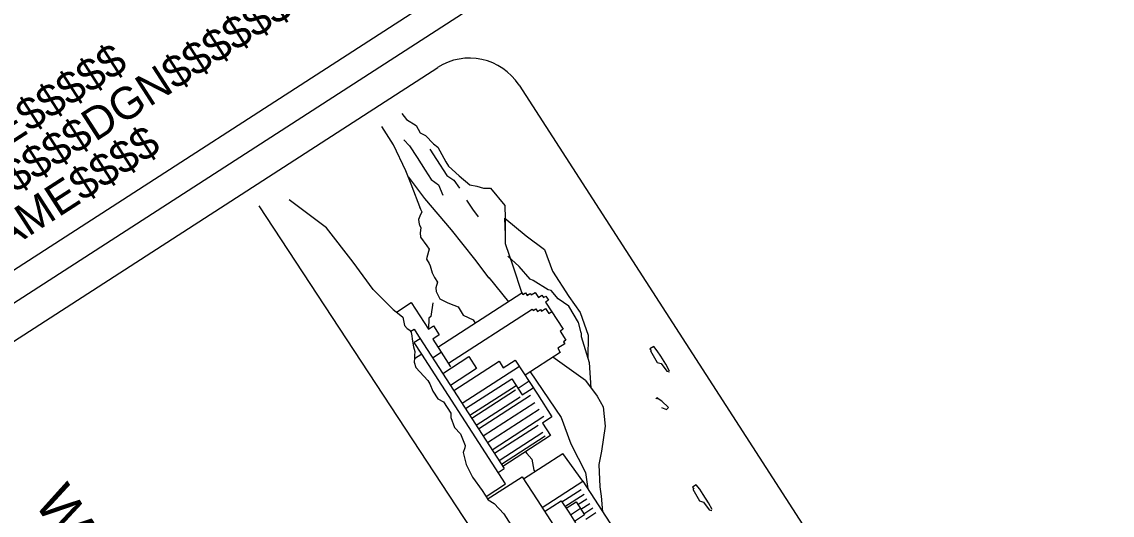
# Model space of a CAD drawing. Extents: x 2160312 to 2162215, y 789569 to 792090.
# Drawn here: x 2160524.6 to 2160714.6, y 791352.1 to 791438.1 of the extents above; entities that cross this region are included whole.
import ezdxf

# ---------------------------------------------------------------- set-up
doc = ezdxf.new("R2010")
doc.units = 0
doc.layers.add('DEV TITLE SHEET CELL', color=7, linetype='Continuous')

msp = doc.modelspace()

# ---------------------------------------------------------------- linework, layer by layer
at = {"layer": 'DEV TITLE SHEET CELL'}
for p, q in [((2161358.45, 791933.98), (2160493.62, 791375.7)), ((2161356.83, 791927.18), (2160500.69, 791374.51)), ((2160507.83, 791372.54), (2160597.07, 791430.14)), ((2160611.25, 791427.06), (2161126.03, 790629.59)), ((2160590.84, 791422.12), (2160591.61, 791421.06)), ((2160589.39, 791416.64), (2160587.32, 791419.85)), ((2160591.61, 791421.06), (2160593.32, 791420.05)), ((2160593.32, 791420.05), (2160594.01, 791418.77)), ((2160591.17, 791417.53), (2160592.16, 791416.49)), ((2160594.01, 791418.77), (2160594.96, 791418.32)), ((2160594.96, 791418.32), (2160596.33, 791416.82)), ((2160591.51, 791412.14), (2160589.39, 791416.64)), ((2160592.16, 791416.49), (2160593.49, 791414.43)), ((2160595.73, 791415.89), (2160596.88, 791414.11)), ((2160596.33, 791416.82), (2160597.09, 791416.26)), ((2160597.09, 791416.26), (2160598.47, 791413.71)), ((2160593.49, 791414.43), (2160594.88, 791412.28)), ((2160596.88, 791414.11), (2160598.69, 791411.3)), ((2160592.44, 791409.8), (2160591.51, 791412.14)), ((2160594.88, 791412.28), (2160595.96, 791410.6)), ((2160598.47, 791413.71), (2160598.95, 791412.96)), ((2160598.95, 791412.96), (2160600.84, 791411.27)), ((2160591.98, 791411.03), (2160594.77, 791407.32)), ((2160595.96, 791410.6), (2160597.22, 791409.69)), ((2160598.69, 791411.3), (2160599.88, 791410.48)), ((2160599.88, 791410.48), (2160600.88, 791409.14)), ((2160600.84, 791411.27), (2160602.67, 791409.67)), ((2160594.12, 791405.4), (2160592.44, 791409.8)), ((2160597.22, 791409.69), (2160597.96, 791407.92)), ((2160602.67, 791409.67), (2160603.88, 791409.45)), ((2160603.88, 791409.45), (2160605.05, 791409.09)), ((2160605.05, 791409.09), (2160606.26, 791409.11)), ((2160606.26, 791409.11), (2160608.75, 791406.12)), ((2160594.77, 791407.32), (2160599.42, 791401.87)), ((2160602.11, 791407.03), (2160603.14, 791405.44)), ((2160608.75, 791406.12), (2160608.83, 791403.82)), ((2160624.28, 791317.21), (2160565.96, 791406.06)), ((2160593.98, 791404.24), (2160593.7, 791403.66)), ((2160593.93, 791405.83), (2160594.3, 791404.97)), ((2160594.3, 791404.97), (2160593.98, 791404.24)), ((2160603.14, 791405.44), (2160604.14, 791404.1)), ((2160593.7, 791403.66), (2160593.84, 791402.82)), ((2160593.84, 791402.82), (2160593.9, 791402.73)), ((2160593.9, 791402.73), (2160594.11, 791402.2)), ((2160608.83, 791403.82), (2160608.84, 791399.49)), ((2160594.11, 791402.2), (2160594, 791401.34)), ((2160594, 791401.34), (2160594.08, 791400.6)), ((2160594.08, 791400.6), (2160595.2, 791399.07)), ((2160599.42, 791401.87), (2160603.5, 791396.72)), ((2160595.2, 791399.07), (2160595.56, 791398.51)), ((2160608.84, 791399.49), (2160610.17, 791395.58)), ((2160595.17, 791397.06), (2160595.11, 791396.76)), ((2160595.11, 791396.76), (2160595.59, 791396.01)), ((2160595.56, 791398.51), (2160595.17, 791397.06)), ((2160603.5, 791396.72), (2160605.96, 791393.42)), ((2160611.25, 791395.44), (2160609.3, 791397.29)), ((2160615.66, 791398.42), (2160617.07, 791394.63)), ((2160595.59, 791396.01), (2160595.74, 791395.57)), ((2160595.74, 791395.57), (2160596.12, 791394.37)), ((2160610.17, 791395.58), (2160611.73, 791390.83)), ((2160613.17, 791393.25), (2160611.25, 791395.44)), ((2160596.12, 791394.37), (2160596.51, 791393.56)), ((2160596.51, 791393.56), (2160597.05, 791392.72)), ((2160605.99, 791393.55), (2160609.4, 791389.33)), ((2160613.7, 791393.02), (2160613.17, 791393.25)), ((2160616.32, 791391.42), (2160613.7, 791393.02)), ((2160617.07, 791394.63), (2160619.91, 791390.25)), ((2160597.05, 791392.72), (2160596.76, 791391.73)), ((2160596.76, 791391.73), (2160596.78, 791391.09)), ((2160596.78, 791391.09), (2160597.47, 791389.81)), ((2160613.34, 791390.51), (2160614.04, 791390.96)), ((2160614.04, 791390.96), (2160614.61, 791390.08)), ((2160616.87, 791391.26), (2160616.32, 791391.42)), ((2160618.06, 791389.81), (2160616.87, 791391.26)), ((2160589.87, 791387.52), (2160592.45, 791389.19)), ((2160592.45, 791389.19), (2160595.45, 791384.55)), ((2160596.2, 791389.12), (2160595.85, 791386.78)), ((2160597.11, 791381.4), (2160611.76, 791390.85)), ((2160597.47, 791389.81), (2160598.85, 791389.11)), ((2160598.85, 791389.11), (2160599.89, 791388.73)), ((2160611.76, 791390.85), (2160611.92, 791390.59)), ((2160611.92, 791390.59), (2160612.36, 791390.87)), ((2160612.36, 791390.87), (2160612.65, 791390.43)), ((2160612.65, 791390.43), (2160613.17, 791390.77)), ((2160612.79, 791390.7), (2160612.84, 791390.55)), ((2160613.17, 791390.77), (2160613.34, 791390.51)), ((2160614.61, 791390.08), (2160615.22, 791390.48)), ((2160615.22, 791390.48), (2160615.51, 791390.04)), ((2160615.51, 791390.04), (2160615.94, 791390.32)), ((2160616.4, 791389.62), (2160615.87, 791389.28)), ((2160615.87, 791389.28), (2160618.93, 791384.55)), ((2160615.94, 791390.32), (2160616.4, 791389.62)), ((2160619.9, 791388.53), (2160618.06, 791389.81)), ((2160619.91, 791390.25), (2160621.9, 791387.45)), ((2160589.32, 791387.96), (2160590.33, 791387.15)), ((2160590.33, 791387.15), (2160591, 791386.61)), ((2160598.96, 791378.62), (2160613.56, 791388.05)), ((2160599.89, 791388.73), (2160600.63, 791388.41)), ((2160600.63, 791388.41), (2160601.53, 791387.01)), ((2160613.56, 791388.05), (2160613.73, 791387.78)), ((2160613.73, 791387.78), (2160614.17, 791388.07)), ((2160614.17, 791388.07), (2160614.46, 791387.63)), ((2160614.46, 791387.63), (2160614.98, 791387.97)), ((2160614.98, 791387.97), (2160615.15, 791387.7)), ((2160615.15, 791387.7), (2160615.85, 791388.16)), ((2160615.85, 791388.16), (2160616.42, 791387.28)), ((2160616.42, 791387.28), (2160616.94, 791387.62)), ((2160621.61, 791385.69), (2160619.9, 791388.53)), ((2160621.9, 791387.45), (2160623.29, 791383.5)), ((2160591, 791386.61), (2160591.29, 791385.17)), ((2160595.54, 791386.45), (2160595.46, 791384.55)), ((2160595.85, 791386.78), (2160595.54, 791386.45)), ((2160601.53, 791387.01), (2160603.28, 791386.15)), ((2160603.28, 791386.15), (2160603.63, 791385.6)), ((2160622.08, 791383.88), (2160621.61, 791385.69)), ((2160591.29, 791385.17), (2160591.77, 791384.67)), ((2160591.77, 791384.67), (2160592.37, 791384.25)), ((2160592.3, 791384.13), (2160592.96, 791384.56)), ((2160592.37, 791384.25), (2160592.58, 791383.41)), ((2160592.58, 791383.41), (2160592.65, 791382.81)), ((2160592.96, 791384.56), (2160594.04, 791382.89)), ((2160595.45, 791384.55), (2160596.33, 791385.11)), ((2160597.35, 791383.54), (2160596.21, 791382.8)), ((2160596.33, 791385.11), (2160597.35, 791383.54)), ((2160618.93, 791384.55), (2160618.4, 791384.21)), ((2160618.4, 791384.21), (2160619.42, 791382.63)), ((2160622.08, 791383.88), (2160622.07, 791383.29)), ((2160623.29, 791383.5), (2160623.23, 791379.45)), ((2160592.65, 791382.81), (2160592.86, 791381.48)), ((2160592.86, 791381.48), (2160593.07, 791380.64)), ((2160594.04, 791382.89), (2160592.99, 791382.21)), ((2160594.29, 791380.19), (2160592.99, 791382.21)), ((2160593.98, 791382.98), (2160598.57, 791375.88)), ((2160596.21, 791382.8), (2160597.68, 791380.52)), ((2160619.21, 791382), (2160617.98, 791381.21)), ((2160619.42, 791382.63), (2160618.98, 791382.35)), ((2160618.98, 791382.35), (2160619.21, 791382)), ((2160622.07, 791383.29), (2160623.45, 791378.74)), ((2160634.71, 791381.55), (2160634.05, 791381.13)), ((2160635.34, 791380.77), (2160634.71, 791381.55)), ((2160593.07, 791380.64), (2160593.02, 791379.96)), ((2160594.29, 791380.19), (2160593.02, 791379.37)), ((2160593.02, 791379.96), (2160593.02, 791379.47)), ((2160608.89, 791357.58), (2160594.29, 791380.19)), ((2160596.19, 791379.56), (2160597.68, 791380.52)), ((2160597.68, 791380.52), (2160599.32, 791377.98)), ((2160597.94, 791376.84), (2160602.5, 791379.78)), ((2160602.5, 791379.78), (2160603.86, 791377.68)), ((2160618.43, 791380.5), (2160612.3, 791376.54)), ((2160622.82, 791375.59), (2160617.14, 791379.67)), ((2160617.98, 791381.21), (2160618.43, 791380.5)), ((2160634.05, 791381.13), (2160634.29, 791380.75)), ((2160634.14, 791380.79), (2160635.31, 791378.76)), ((2160635.95, 791379.83), (2160635.34, 791380.77)), ((2160636.85, 791378.43), (2160635.95, 791379.83)), ((2160593.02, 791379.47), (2160592.97, 791378.79)), ((2160592.97, 791378.79), (2160593.26, 791377.84)), ((2160593.26, 791377.84), (2160595.34, 791375.62)), ((2160603.86, 791377.68), (2160599.3, 791374.74)), ((2160599.87, 791373.86), (2160607.76, 791378.95)), ((2160611.33, 791378.03), (2160601.34, 791371.58)), ((2160607.76, 791378.95), (2160608.49, 791377.81)), ((2160608.49, 791377.81), (2160610.6, 791379.17)), ((2160610.6, 791379.17), (2160614.45, 791373.21)), ((2160623.45, 791378.74), (2160623.77, 791374.24)), ((2160635.31, 791378.76), (2160635.99, 791378.54)), ((2160635.99, 791378.54), (2160636.99, 791377.2)), ((2160637.48, 791377.25), (2160636.85, 791378.43)), ((2160598.57, 791375.88), (2160608.64, 791360.27)), ((2160601.91, 791370.7), (2160609.97, 791375.91)), ((2160609.97, 791375.91), (2160611.78, 791373.11)), ((2160613.19, 791377.12), (2160618.61, 791369.17)), ((2160636.99, 791377.2), (2160637.45, 791377.1)), ((2160595.34, 791375.62), (2160595.71, 791375.04)), ((2160595.71, 791375.04), (2160596.22, 791373.75)), ((2160610.76, 791374.68), (2160602.7, 791369.48)), ((2160610.64, 791373.94), (2160603, 791369.01)), ((2160612.99, 791375.46), (2160611.07, 791374.22)), ((2160611.78, 791373.11), (2160613.71, 791374.35)), ((2160622.82, 791375.59), (2160624.88, 791372.89)), ((2160596.22, 791373.75), (2160597.11, 791372.38)), ((2160597.11, 791372.38), (2160598.09, 791371.87)), ((2160611.44, 791372.69), (2160603.8, 791367.76)), ((2160613.25, 791372.98), (2160604.21, 791367.14)), ((2160614.45, 791373.21), (2160616.99, 791369.27)), ((2160624.88, 791372.89), (2160625.89, 791370.99)), ((2160635.38, 791372.59), (2160635.1, 791372.41)), ((2160635.5, 791372.4), (2160635.38, 791372.59)), ((2160636.15, 791372.02), (2160635.5, 791372.4)), ((2160637.27, 791370.9), (2160636.15, 791372.02)), ((2160598.09, 791371.87), (2160599.34, 791369.92)), ((2160614.01, 791371.7), (2160605.01, 791365.89)), ((2160614.78, 791370.56), (2160605.76, 791364.73)), ((2160625.89, 791370.99), (2160626.25, 791367.67)), ((2160636.07, 791370.91), (2160636.96, 791370.56)), ((2160636.96, 791370.56), (2160637.27, 791370.9)), ((2160599.34, 791369.92), (2160599.37, 791369.13)), ((2160599.37, 791369.13), (2160599.99, 791367.42)), ((2160615.59, 791369.31), (2160606.56, 791363.49)), ((2160616.99, 791369.27), (2160615.33, 791368.19)), ((2160615.33, 791368.19), (2160616.74, 791366)), ((2160618.61, 791369.17), (2160620.27, 791364.55)), ((2160599.99, 791367.42), (2160601.03, 791366.3)), ((2160601.03, 791366.3), (2160601.87, 791364.25)), ((2160614.6, 791367.79), (2160606.97, 791362.86)), ((2160615.41, 791366.55), (2160607.77, 791361.62)), ((2160626.25, 791367.67), (2160625.64, 791363.28)), ((2160615.81, 791365.92), (2160608.17, 791360.99)), ((2160616.74, 791366), (2160608.41, 791360.62)), ((2160620.27, 791364.55), (2160622.81, 791359.58)), ((2160601.79, 791363.87), (2160601.51, 791363.04)), ((2160601.51, 791363.04), (2160602.05, 791360.96)), ((2160601.87, 791364.25), (2160601.79, 791363.87)), ((2160612.03, 791358.48), (2160618.87, 791362.9)), ((2160612.4, 791363.2), (2160612.59, 791362.91)), ((2160612.59, 791362.91), (2160613.5, 791361.9)), ((2160622.36, 791358.07), (2160618.87, 791362.9)), ((2160625.64, 791363.28), (2160625.14, 791360.96)), ((2160602.05, 791360.96), (2160603.15, 791358.75)), ((2160613.5, 791361.9), (2160613.81, 791359.99)), ((2160625.14, 791360.96), (2160625.31, 791357.07)), ((2160603.15, 791358.75), (2160604.82, 791356.41)), ((2160605.7, 791354.9), (2160611.8, 791358.84)), ((2160607.59, 791359.59), (2160608.64, 791360.27)), ((2160611.8, 791358.84), (2160614.41, 791354.8)), ((2160613.81, 791359.99), (2160613.99, 791359.75)), ((2160622.81, 791359.58), (2160623.23, 791356.71)), ((2160605.54, 791355.41), (2160608.89, 791357.58)), ((2160615.26, 791353.49), (2160622.36, 791358.07)), ((2160622.36, 791358.07), (2160627.68, 791349.83)), ((2160625.31, 791357.07), (2160625.58, 791355.46)), ((2160642.11, 791357.43), (2160641.46, 791357.01)), ((2160641.46, 791357.01), (2160641.7, 791356.64)), ((2160642.75, 791356.65), (2160642.11, 791357.43)), ((2160604.82, 791356.41), (2160605.85, 791354.81)), ((2160618.73, 791354.45), (2160622.06, 791356.6)), ((2160619.25, 791353.65), (2160622.57, 791355.8)), ((2160621.52, 791353.98), (2160623.09, 791354.99)), ((2160625.58, 791355.46), (2160625.79, 791352.72)), ((2160641.55, 791356.67), (2160642.72, 791354.65)), ((2160643.35, 791355.72), (2160642.75, 791356.65)), ((2160644.26, 791354.31), (2160643.35, 791355.72)), ((2160605.85, 791354.81), (2160606.9, 791354.19)), ((2160606.9, 791354.19), (2160608.58, 791352.35)), ((2160614.41, 791354.8), (2160617.24, 791350.42)), ((2160615.71, 791352.79), (2160618.6, 791354.65)), ((2160618.6, 791354.65), (2160619.9, 791352.64)), ((2160619.45, 791353.34), (2160621.2, 791354.47)), ((2160620.19, 791352.2), (2160621.94, 791353.33)), ((2160621.2, 791354.47), (2160622.67, 791352.19)), ((2160622.04, 791353.17), (2160623.61, 791354.19)), ((2160622.56, 791352.37), (2160624.13, 791353.39)), ((2160642.72, 791354.65), (2160643.39, 791354.42)), ((2160643.39, 791354.42), (2160644.39, 791353.08)), ((2160644.89, 791353.13), (2160644.26, 791354.31)), ((2160644.39, 791353.08), (2160644.85, 791352.98)), ((2160608.58, 791352.35), (2160610.2, 791349.83)), ((2160619.9, 791352.64), (2160621.09, 791350.8)), ((2160622.67, 791352.19), (2160620.92, 791351.06)), ((2160622.9, 791351.45), (2160624.65, 791352.58))]:
    msp.add_line(p, q, dxfattribs=at)
for points in [[(2160589.32, 791387.96), (2160585.84, 791391.44), (2160582.35, 791396.25), (2160577.67, 791402.23), (2160571.21, 791407.1)], [(2160608.88, 791401), (2160608.79, 791403.86), (2160612.5, 791400.81), (2160615.66, 791398.42)]]:
    msp.add_lwpolyline(points, dxfattribs=at)
msp.add_arc((2160602.61, 791421.48), 10.29, 32.8434, 122.8434, dxfattribs=at)

# ---------------------------------------------------------------- texts
for s, height, rotation, p in [('$$$$$$$$$$$$$$$$DGN$$$$$$$$$$$$$$$$', 5.584, 32.8031, (2160481.54, 791381.13)), ('$$$$$$SYSTIME$$$$$', 5.584, 32.8031, (2160477.43, 791387.51)), ('$$$$USERNAME$$$$', 5.584, 32.8031, (2160485.65, 791374.76)), ('WORK ZONE SAFETY & MOBILITY', 7, 302.8031, (2160526.62, 791354.43))]:
    msp.add_text(s, height=height, rotation=rotation, dxfattribs=at).set_placement(p)

doc.saveas('drawing.dxf')
